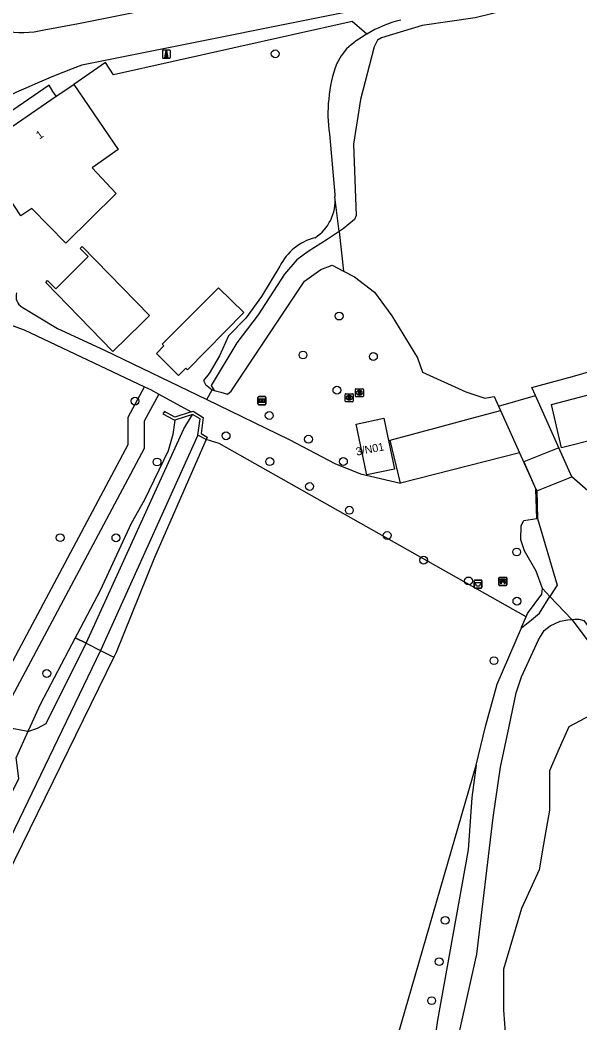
# Model space of a CAD drawing. Extents: x 164494 to 166241, y 382475 to 384494.
# Drawn here: x 165408.9 to 165478.8, y 383963 to 384088.3 of the extents above; entities that cross this region are included whole.
import ezdxf

# ---------------------------------------------------------------- set-up
doc = ezdxf.new("R2010")
doc.units = 0
for name, color, linetype in [('IMGEO_Afvalbak', 7, 'Continuous'), ('IMGEO_Bank', 7, 'Continuous'), ('IMGEO_Boom', 7, 'Continuous'), ('IMGEO_Erf', 7, 'Continuous'), ('IMGEO_Grasland_agrarisch', 7, 'Continuous'), ('IMGEO_Grasland_overig', 7, 'Continuous'), ('IMGEO_Groenvoorziening', 7, 'Continuous'), ('IMGEO_Informatiebord', 7, 'Continuous'), ('IMGEO_Kademuur', 7, 'Continuous'), ('IMGEO_Laagspanningsmast', 7, 'Continuous'), ('IMGEO_Loofbos', 7, 'Continuous'), ('IMGEO_Meer_plas_ven_vijver', 7, 'Continuous'), ('IMGEO_Muur', 7, 'Continuous'), ('IMGEO_Oever', 7, 'Continuous'), ('IMGEO_Pand', 7, 'Continuous'), ('IMGEO_Pand_nummerreeks', 7, 'Continuous'), ('IMGEO_Rijbaan_lokaal_gesloten', 7, 'Continuous'), ('IMGEO_Rioolput', 7, 'Continuous'), ('IMGEO_Rivier', 7, 'Continuous'), ('IMGEO_Stuw', 7, 'Continuous'), ('IMGEO_Voetpad_halfverhard', 7, 'Continuous'), ('IMGEO_Voetpad_open', 7, 'Continuous'), ('IMGEO_Waterloop', 7, 'Continuous')]:
    doc.layers.add(name, color=color, linetype=linetype)

msp = doc.modelspace()

# ---------------------------------------------------------------- linework, layer by layer
at = {"layer": 'IMGEO_Afvalbak'}
for p, q in [((165465.62, 384017.39), (165465.62, 384018.19)), ((165465.62, 384018.19), (165465.62, 384017.39)), ((165465.72, 384018.29), (165466.5, 384018.29)), ((165466.5, 384018.29), (165465.72, 384018.29)), ((165466.6, 384018.19), (165466.6, 384017.39)), ((165466.6, 384017.39), (165466.6, 384018.19)), ((165466.5, 384017.29), (165465.72, 384017.29)), ((165465.72, 384017.29), (165466.5, 384017.29))]:
    msp.add_line(p, q, dxfattribs=at)
msp.add_lwpolyline([(165465.76, 384018), (165466.46, 384018), (165466.31, 384017.53), (165465.91, 384017.53), (165465.76, 384018)], dxfattribs=at)
for centre, start, end in [((165465.72, 384018.19), 90, 180), ((165465.72, 384018.19), 90, 180), ((165466.5, 384018.19), 0, 90), ((165466.5, 384018.19), 360, 90), ((165465.72, 384017.39), 180, 270), ((165465.72, 384017.39), 180, 270), ((165466.5, 384017.39), 270, 0), ((165466.5, 384017.39), 270, 0)]:
    msp.add_arc(centre, 0.1, start, end, dxfattribs=at)
at = {"layer": 'IMGEO_Bank'}
for p, q in [((165468.72, 384017.69), (165468.72, 384018.54)), ((165468.72, 384018.54), (165468.72, 384017.69)), ((165468.79, 384018.62), (165469.63, 384018.62)), ((165469.63, 384018.62), (165468.79, 384018.62)), ((165469.41, 384018.02), (165469.02, 384018.02)), ((165469.03, 384018.13), (165469.03, 384018.23)), ((165469.07, 384018.23), (165469.07, 384018.13)), ((165469.36, 384018.24), (165469.08, 384018.24)), ((165469.08, 384018.12), (165469.36, 384018.12)), ((165469.36, 384018.13), (165469.36, 384018.23)), ((165469.41, 384018.23), (165469.41, 384018.13)), ((165469.72, 384018.55), (165469.72, 384017.7)), ((165469.72, 384017.7), (165469.72, 384018.55)), ((165469.64, 384017.62), (165468.8, 384017.62)), ((165468.8, 384017.62), (165469.64, 384017.62))]:
    msp.add_line(p, q, dxfattribs=at)
for points in [[(165468.96, 384018.02), (165468.82, 384018.02), (165468.93, 384018.12), (165469.02, 384018.12)], [(165469.02, 384018.24), (165468.93, 384018.24), (165468.93, 384018.4), (165469.5, 384018.4), (165469.5, 384018.24), (165469.41, 384018.24)], [(165469.01, 384018.01), (165469.01, 384017.8), (165468.97, 384017.8), (165468.97, 384018.01)], [(165469.41, 384018.12), (165469.5, 384018.12), (165469.61, 384018.02), (165469.47, 384018.02)], [(165469.46, 384018.01), (165469.46, 384017.8), (165469.42, 384017.8), (165469.42, 384018.01)]]:
    msp.add_lwpolyline(points, dxfattribs=at)
for centre, radius, start, end in [((165468.79, 384018.54), 0.0779, 92.4484, 184.2845), ((165468.79, 384018.54), 0.0779, 92.4484, 184.2845), ((165468.96, 384018.01), 0.00671, 2.8957, 87.1043), ((165469.02, 384018.01), 0.00671, 92.8957, 177.1043), ((165469.02, 384018.23), 0.00671, 2.8957, 87.1043), ((165469.02, 384018.13), 0.00671, 272.8957, 357.1043), ((165469.08, 384018.23), 0.00671, 92.8957, 177.1043), ((165469.08, 384018.13), 0.00671, 182.8957, 267.1043), ((165469.36, 384018.23), 0.00671, 2.8957, 87.1043), ((165469.36, 384018.13), 0.00671, 272.8957, 357.1043), ((165469.41, 384018.23), 0.00671, 92.8957, 177.1043), ((165469.41, 384018.13), 0.00671, 182.8957, 267.1043), ((165469.41, 384018.01), 0.00671, 2.8957, 87.1043), ((165469.47, 384018.01), 0.00671, 92.8957, 177.1043), ((165469.64, 384018.54), 0.0779, 2.4484, 94.2845), ((165469.64, 384018.54), 0.0779, 2.4484, 94.2845), ((165468.79, 384017.7), 0.0779, 182.4484, 274.2845), ((165468.79, 384017.7), 0.0779, 182.4484, 274.2845), ((165469.64, 384017.7), 0.0779, 272.4484, 4.2845), ((165469.64, 384017.7), 0.0779, 272.4484, 4.2845)]:
    msp.add_arc(centre, radius, start, end, dxfattribs=at)
at = {"layer": 'IMGEO_Boom'}
for centre in [(165440.77, 384084.04), (165448.76, 384051.27), (165444.24, 384046.41), (165453.04, 384046.21), (165448.48, 384042.01), (165423.25, 384040.64), (165440.02, 384038.84), (165434.63, 384036.31), (165444.93, 384035.88), (165426.01, 384033.03), (165440.09, 384033.09), (165449.29, 384033.1), (165445.06, 384029.98), (165450.03, 384027.01), (165413.91, 384023.58), (165420.87, 384023.56), (165454.76, 384023.86), (165470.94, 384021.8), (165459.32, 384020.77), (165464.92, 384018.18), (165470.97, 384015.65), (165468.1, 384008.22), (165412.23, 384006.62), (165462.01, 383975.77), (165461.26, 383970.61), (165460.32, 383965.74)]:
    msp.add_circle(centre, 0.489, dxfattribs=at)
at = {"layer": 'IMGEO_Erf'}
for points in [[(165449.69, 384084.66), (165448.99, 384083.8), (165448.46, 384082.83)], [(165447.55, 384074.05), (165448.2, 384066.46), (165448.24, 384066.18)], [(165441.35, 384057.51), (165439.04, 384053.71), (165437.08, 384051), (165434.93, 384048.82), (165433.83, 384046.32), (165432.51, 384044.11), (165431.83, 384043.24), (165432.06, 384042.7), (165432.89, 384042.04)]]:
    msp.add_lwpolyline(points, dxfattribs=at)
for centre, radius, start, end in [((165460.36, 384072.73), 16.01, 120.6716, 131.8064), ((165464.09, 384076.96), 16.7, 159.419, 175.1062), ((165464.24, 384076.59), 16.88, 173.9109, 188.6552), ((165442.76, 384065.68), 5.5, 302.8365, 5.2124), ((165447.45, 384054.45), 6.83, 104.5317, 153.3804)]:
    msp.add_arc(centre, radius, start, end, dxfattribs=at)
at = {"layer": 'IMGEO_Grasland_agrarisch'}
for points in [[(165432.13, 384035.84), (165425.7, 384021.1), (165420.91, 384009.22), (165420.6, 384008.64)], [(165471.52, 384012.31), (165471.56, 384012.41), (165472.11, 384013.7)], [(165420.6, 384008.64), (165397.65, 383961.84), (165387.56, 383941.91)]]:
    msp.add_lwpolyline(points, dxfattribs=at)
at = {"layer": 'IMGEO_Grasland_overig'}
for points in [[(165404.24, 384001.22), (165422.41, 384035.22), (165422.41, 384038.64), (165424.44, 384042.44)], [(165426.22, 384041.52), (165424.41, 384038.14), (165424.41, 384034.72), (165406.11, 384000.48)]]:
    msp.add_lwpolyline(points, dxfattribs=at)
at = {"layer": 'IMGEO_Groenvoorziening'}
for points in [[(165452.2, 384086.5), (165450.37, 384088.08), (165420.58, 384081.41), (165419.58, 384082.94), (165415.6, 384080.22)], [(165413.42, 384078.73), (165413, 384079.33), (165412.51, 384080.13), (165404.07, 384074.33), (165403.55, 384075.18), (165393.46, 384068.19), (165394.61, 384066.34)], [(165432.21, 384040.83), (165432.89, 384042.04)], [(165432.89, 384042.04), (165433.16, 384041.98)], [(165428.23, 384038.26), (165427.99, 384036.47), (165427.4, 384034.45), (165424.46, 384028.31), (165422.77, 384025.34), (165418.89, 384016.97), (165416.08, 384011.62), (165415.79, 384011.09)], [(165474.15, 384017.24), (165475.1, 384016.25)], [(165415.79, 384011.09), (165411.41, 384002.76), (165410.16, 384000), (165409.88, 383999.37)]]:
    msp.add_lwpolyline(points, dxfattribs=at)
msp.add_arc((165460.37, 384072.72), 16.02, 104.1806, 120.6638, dxfattribs=at)
at = {"layer": 'IMGEO_Informatiebord'}
for p, q in [((165438.62, 384040.3), (165438.62, 384041.1)), ((165438.62, 384041.1), (165438.62, 384040.3)), ((165438.72, 384041.2), (165439.51, 384041.2)), ((165439.51, 384041.2), (165438.72, 384041.2)), ((165439.61, 384041.1), (165439.61, 384040.3)), ((165439.61, 384040.3), (165439.61, 384041.1)), ((165439.51, 384040.2), (165438.72, 384040.2)), ((165438.72, 384040.2), (165439.51, 384040.2))]:
    msp.add_line(p, q, dxfattribs=at)
for points in [[(165438.72, 384040.94), (165439.51, 384040.94), (165439.51, 384040.47), (165438.72, 384040.47), (165438.72, 384040.94)], [(165438.79, 384040.87), (165438.79, 384040.54), (165439.06, 384040.54), (165439.06, 384040.75), (165439.17, 384040.75), (165439.17, 384040.54), (165439.44, 384040.54), (165439.44, 384040.87), (165439.17, 384040.87), (165439.17, 384040.79), (165439.06, 384040.79), (165439.06, 384040.87), (165438.79, 384040.87)]]:
    msp.add_lwpolyline(points, dxfattribs=at)
for centre, start, end in [((165438.72, 384041.1), 90, 180), ((165438.72, 384041.1), 90, 180), ((165439.51, 384041.1), 0, 90), ((165439.51, 384041.1), 360, 90), ((165438.72, 384040.3), 180, 270), ((165438.72, 384040.3), 180, 270), ((165439.51, 384040.3), 270, 0), ((165439.51, 384040.3), 270, 0)]:
    msp.add_arc(centre, 0.1, start, end, dxfattribs=at)
at = {"layer": 'IMGEO_Kademuur'}
for points in [[(165473.35, 384029.64), (165473.45, 384029.42), (165473.55, 384025.97)], [(165473.45, 384025.98), (165473.35, 384029.64)], [(165473.55, 384025.97), (165473.45, 384025.98)]]:
    msp.add_lwpolyline(points, dxfattribs=at)
at = {"layer": 'IMGEO_Laagspanningsmast'}
for p, q in [((165426.67, 384084.41), (165426.67, 384083.57)), ((165426.67, 384084.41), (165426.67, 384083.57)), ((165427.59, 384084.5), (165426.75, 384084.5)), ((165427.59, 384084.5), (165426.75, 384084.5)), ((165427.12, 384084.18), (165427.07, 384083.93)), ((165427.12, 384084.19), (165427.21, 384084.19)), ((165427.16, 384084.1), (165427.12, 384084.18)), ((165427.13, 384084.18), (165427.17, 384084.11)), ((165427.21, 384084.18), (165427.13, 384084.18)), ((165427.17, 384084.11), (165427.21, 384084.18)), ((165427.22, 384084.18), (165427.17, 384084.1)), ((165427.27, 384083.93), (165427.22, 384084.18)), ((165427.67, 384083.58), (165427.67, 384084.42)), ((165427.67, 384083.58), (165427.67, 384084.42)), ((165426.76, 384083.5), (165427.6, 384083.5)), ((165426.76, 384083.5), (165427.6, 384083.5)), ((165427.33, 384083.61), (165427, 384083.61)), ((165427.06, 384083.9), (165427.01, 384083.64)), ((165427.01, 384083.64), (165427.16, 384083.8)), ((165427.17, 384083.79), (165427.02, 384083.63)), ((165427.02, 384083.63), (165427.32, 384083.63)), ((165427.16, 384083.8), (165427.06, 384083.9)), ((165427.07, 384083.93), (165427.16, 384084.1)), ((165427.07, 384083.91), (165427.17, 384083.81)), ((165427.26, 384083.91), (165427.07, 384083.91)), ((165427.17, 384084.09), (165427.08, 384083.93)), ((165427.08, 384083.93), (165427.26, 384083.93)), ((165427.17, 384084.1), (165427.27, 384083.93)), ((165427.26, 384083.93), (165427.17, 384084.09)), ((165427.17, 384083.81), (165427.26, 384083.91)), ((165427.32, 384083.63), (165427.17, 384083.79)), ((165427.27, 384083.9), (165427.18, 384083.8)), ((165427.18, 384083.8), (165427.32, 384083.64)), ((165427.32, 384083.64), (165427.27, 384083.9))]:
    msp.add_line(p, q, dxfattribs=at)
for points in [[(165427, 384083.61), (165426.99, 384083.55), (165426.97, 384083.55), (165427.14, 384084.44), (165427.17, 384084.45), (165427.19, 384084.44), (165427.37, 384083.55), (165427.34, 384083.55), (165427.33, 384083.61)], [(165427.21, 384084.19), (165427.17, 384084.43), (165427.12, 384084.19)]]:
    msp.add_lwpolyline(points, dxfattribs=at)
for centre, start, end in [((165426.75, 384084.42), 92.4484, 184.2845), ((165426.75, 384084.42), 92.4484, 184.2845), ((165427.59, 384084.42), 2.4484, 94.2845), ((165427.59, 384084.42), 2.4484, 94.2845), ((165426.75, 384083.58), 182.4484, 274.2845), ((165426.75, 384083.58), 182.4484, 274.2845), ((165427.59, 384083.58), 272.4484, 4.2845), ((165427.59, 384083.58), 272.4484, 4.2845)]:
    msp.add_arc(centre, 0.0779, start, end, dxfattribs=at)
at = {"layer": 'IMGEO_Loofbos'}
for points in [[(165477.83, 384013.38), (165482.39, 384007.27), (165486.63, 384002.04), (165487.13, 384001.42)], [(165432.52, 383879.96), (165465.88, 383995.16)]]:
    msp.add_lwpolyline(points, dxfattribs=at)
at = {"layer": 'IMGEO_Meer_plas_ven_vijver'}
msp.add_lwpolyline([(165480.2, 384001.42), (165477.44, 383999.97), (165476.1, 383996.88), (165475.04, 383994.47), (165475.04, 383989.53), (165474.3, 383985.31), (165473.73, 383982.1), (165471.55, 383977.25), (165469.3, 383969.67), (165469.3, 383964.56), (165469.55, 383961.22), (165470.89, 383959.32), (165472.93, 383958.13), (165475.5, 383958.13), (165480.95, 383958.3)], dxfattribs=at)
at = {"layer": 'IMGEO_Muur'}
for points in [[(165430.27, 384039.31), (165428.21, 384038.62), (165426.94, 384039.34), (165426.75, 384039.04), (165428.08, 384038.34), (165428.23, 384038.26)], [(165430.27, 384039.31), (165430.5, 384039.39), (165431.77, 384038.6), (165431.52, 384036.59), (165432.26, 384036.16), (165432.13, 384035.84)], [(165430.45, 384038.96), (165428.23, 384038.26)], [(165431.12, 384036.4), (165431.4, 384038.43), (165430.45, 384038.96)], [(165432.13, 384035.84), (165431.12, 384036.4)]]:
    msp.add_lwpolyline(points, dxfattribs=at)
at = {"layer": 'IMGEO_Oever'}
for points in [[(165448.74, 384061.82), (165448.24, 384066.18)], [(165417.14, 384010.41), (165415.79, 384011.09)], [(165418.94, 384009.5), (165420.6, 384008.64)]]:
    msp.add_lwpolyline(points, dxfattribs=at)
at = {"layer": 'IMGEO_Pand'}
for points in [[(165415.6, 384080.22), (165421.16, 384072.09), (165417.91, 384069.8), (165420.92, 384066.58), (165414.62, 384060.38), (165410.36, 384064.72), (165408.99, 384063.79), (165403.58, 384072), (165413.42, 384078.73)], [(165413.42, 384078.73), (165415.6, 384080.22)], [(165424.1, 384050.37), (165420.47, 384046.84), (165412.1, 384055.45), (165412.34, 384055.7), (165413.35, 384054.69), (165417.39, 384058.72), (165416.39, 384059.72), (165416.64, 384059.97), (165425.07, 384051.32), (165424.1, 384050.37)], [(165425.93, 384046.61), (165426.86, 384047.53), (165426.65, 384047.74), (165433.7, 384054.8), (165436.84, 384051.71), (165429.8, 384044.56), (165429.59, 384044.77), (165428.67, 384043.86), (165425.93, 384046.61)], [(165491.94, 384044.59), (165494.08, 384034.6), (165485.88, 384032.75), (165485.64, 384034.07), (165485.11, 384036.98), (165476.53, 384034.79), (165475.28, 384040.21), (165482.1, 384042.01), (165491.94, 384044.59)], [(165456.43, 384030.39), (165455.12, 384035.77), (165461.8, 384037.57), (165464.71, 384038.34), (165468.92, 384039.47)], [(165468.92, 384039.47), (165470.96, 384034.95), (165471.3, 384034.18)], [(165452.19, 384031.58), (165450.88, 384037.77), (165454.35, 384038.53), (165454.93, 384035.72), (165455.67, 384032.14), (165452.22, 384031.44), (165452.19, 384031.58)], [(165471.3, 384034.18), (165456.43, 384030.39)]]:
    msp.add_lwpolyline(points, dxfattribs=at)
at = {"layer": 'IMGEO_Rijbaan_lokaal_gesloten'}
for points in [[(165411.91, 384087.02), (165416.2, 384087.82), (165455.96, 384095.8)], [(165456.98, 384090.71), (165416.61, 384082.6)]]:
    msp.add_lwpolyline(points, dxfattribs=at)
for centre, radius, start, end in [((165408.98, 384099.66), 12.97, 260.4155, 283.0716), ((165456.82, 383973.93), 115.88, 110.3071, 120.2751)]:
    msp.add_arc(centre, radius, start, end, dxfattribs=at)
at = {"layer": 'IMGEO_Rioolput'}
for p, q in [((165450.79, 384041.26), (165450.79, 384042.11)), ((165450.86, 384042.19), (165451.71, 384042.19)), ((165451.28, 384041.96), (165451.3, 384041.96)), ((165451.79, 384042.11), (165451.79, 384041.26)), ((165449.52, 384040.64), (165449.52, 384041.49)), ((165449.59, 384041.57), (165450.44, 384041.57)), ((165450.44, 384040.57), (165449.59, 384040.57)), ((165450.03, 384040.79), (165450, 384040.79)), ((165450.01, 384041.35), (165450.03, 384041.35)), ((165450.52, 384041.49), (165450.52, 384040.64)), ((165451.71, 384041.18), (165450.86, 384041.18)), ((165451.3, 384041.41), (165451.27, 384041.41))]:
    msp.add_line(p, q, dxfattribs=at)
for points in [[(165450.79, 384041.26), (165450.79, 384042.11)], [(165450.86, 384042.19), (165451.71, 384042.19)], [(165451.38, 384041.88), (165451.12, 384041.88), (165451.12, 384041.48)], [(165451.12, 384041.48), (165451.25, 384041.48), (165451.25, 384041.65), (165451.26, 384041.65)], [(165451.3, 384041.8), (165451.25, 384041.8), (165451.25, 384041.72)], [(165451.25, 384041.72), (165451.3, 384041.72)], [(165451.31, 384041.62), (165451.38, 384041.48), (165451.52, 384041.48), (165451.45, 384041.61)], [(165451.79, 384042.11), (165451.79, 384041.26)], [(165449.52, 384040.64), (165449.52, 384041.49)], [(165449.59, 384041.57), (165450.44, 384041.57)], [(165450.44, 384040.57), (165449.59, 384040.57)], [(165450.11, 384041.26), (165449.85, 384041.27), (165449.85, 384040.87)], [(165449.85, 384040.87), (165449.98, 384040.87), (165449.98, 384041.03), (165449.99, 384041.03)], [(165450.03, 384041.19), (165449.98, 384041.19), (165449.98, 384041.1)], [(165449.98, 384041.1), (165450.03, 384041.1)], [(165450.04, 384041), (165450.11, 384040.87), (165450.25, 384040.87), (165450.18, 384040.99)], [(165450.52, 384041.49), (165450.52, 384040.64)], [(165451.71, 384041.18), (165450.86, 384041.18)]]:
    msp.add_lwpolyline(points, dxfattribs=at)
for centre, radius, start, end in [((165450.86, 384042.11), 0.0765, 91.552, 178.448), ((165450.86, 384042.11), 0.0765, 91.552, 178.448), ((165451.26, 384041.59), 0.0533, 26.0293, 88.6989), ((165451.31, 384041.71), 0.0964, 77.0061, 93.1865), ((165451.28, 384041.91), 0.19, 274.7715, 282.9687), ((165451.32, 384041.76), 0.0378, 276.6634, 79.6772), ((165451.38, 384041.77), 0.109, 350.3612, 89.416), ((165451.37, 384041.77), 0.112, 277.5842, 350.9817), ((165451.36, 384041.56), 0.108, 29.5134, 73.7905), ((165451.71, 384042.11), 0.0765, 1.552, 88.448), ((165451.71, 384042.11), 0.0765, 1.552, 88.448), ((165449.59, 384041.49), 0.0765, 91.552, 178.448), ((165449.59, 384041.49), 0.0765, 91.552, 178.448), ((165449.59, 384040.64), 0.0765, 181.552, 268.448), ((165449.59, 384040.64), 0.0765, 181.552, 268.448), ((165449.99, 384040.98), 0.0533, 26.0293, 88.6989), ((165450.04, 384041.09), 0.0964, 77.0061, 93.1865), ((165450.01, 384041.29), 0.19, 274.7715, 282.9687), ((165450.05, 384041.15), 0.0378, 276.6634, 79.6772), ((165450.11, 384041.15), 0.109, 350.3612, 89.416), ((165450.1, 384041.15), 0.112, 277.5842, 350.9817), ((165450.09, 384040.94), 0.108, 29.5134, 73.7905), ((165450.44, 384041.49), 0.0765, 1.552, 88.448), ((165450.44, 384041.49), 0.0765, 1.552, 88.448), ((165450.44, 384040.64), 0.0765, 271.552, 358.448), ((165450.44, 384040.64), 0.0765, 271.552, 358.448), ((165450.86, 384041.26), 0.0765, 181.552, 268.448), ((165450.86, 384041.26), 0.0765, 181.552, 268.448), ((165451.71, 384041.26), 0.0765, 271.552, 358.448), ((165451.71, 384041.26), 0.0765, 271.552, 358.448)]:
    msp.add_arc(centre, radius, start, end, dxfattribs=at)
for centre, major_axis, ratio, start_param, end_param in [((165451.27, 384041.68), (-0.387, 0.002), 0.722429, 4.712389, 7.853982), ((165451.3, 384041.68), (-0.39, 0.002), 0.717154, 1.570796, 4.712389), ((165450, 384041.07), (-0.387, 0.002), 0.722429, 4.712389, 7.853982), ((165450.03, 384041.07), (-0.39, 0.002), 0.717154, 1.570796, 4.712389)]:
    msp.add_ellipse(centre, major_axis=major_axis, ratio=ratio, start_param=start_param, end_param=end_param, dxfattribs=at)
at = {"layer": 'IMGEO_Rivier'}
for points in [[(165474.83, 384091.12), (165469.52, 384089.43), (165465.75, 384088.54), (165459.14, 384087.57), (165454.07, 384086.05), (165453.57, 384085.73), (165453.13, 384084.89), (165451.41, 384078.33), (165450.57, 384072.76), (165450.89, 384063.84), (165450.66, 384063.34), (165449.28, 384062.17), (165448.74, 384061.82)], [(165473.27, 384041.33), (165472.82, 384042.34), (165473.75, 384042.59), (165477.9, 384043.72), (165483.77, 384045.44), (165486.01, 384048.77), (165487.52, 384053.23), (165488.1, 384062.16), (165487.05, 384069.95), (165486.01, 384074.23), (165486.3, 384078.74), (165489.65, 384082.75), (165493.52, 384085.76), (165495.37, 384086.22), (165499.76, 384086.15), (165510.96, 384086.71), (165512.96, 384086.35), (165513.67, 384084.92)], [(165448.74, 384061.82), (165449.32, 384056.89)], [(165449.32, 384056.89), (165450.67, 384056.19), (165453.18, 384054.24), (165455.36, 384051.28), (165458.53, 384046.07), (165459.18, 384044.24), (165464.57, 384041.81), (165466.96, 384041.03), (165468.13, 384041.22), (165468.68, 384040)], [(165468.68, 384040), (165473.27, 384041.33)], [(165554.47, 383924.18), (165553.46, 383924.3), (165551.79, 383925.29), (165548.66, 383927.88), (165543.58, 383932.37), (165541.37, 383934.81), (165535.29, 383951.85), (165527.54, 383967.82), (165514.92, 383987.28), (165498.19, 384008.96), (165488.46, 384021.89), (165477.84, 384031.18), (165473.27, 384041.33)], [(165468.68, 384040), (165468.92, 384039.47)], [(165473.55, 384025.97), (165476, 384017.67), (165475.1, 384016.25)], [(165475.1, 384016.25), (165477.83, 384013.38)], [(165477.83, 384013.38), (165478.22, 384013.42), (165478.69, 384013.39), (165479.32, 384013.23), (165481.89, 384009.78), (165483.64, 384007.37), (165485.78, 384004.64), (165486.29, 384003.59), (165486.43, 384003.01), (165486.83, 384002.56), (165487.34, 384001.98), (165487.38, 384001.58), (165487.23, 384001.3)]]:
    msp.add_lwpolyline(points, dxfattribs=at)
at = {"layer": 'IMGEO_Stuw'}
for points in [[(165468.68, 384040), (165473.27, 384041.33)], [(165415.79, 384011.09), (165417.14, 384010.41), (165418.94, 384009.5), (165420.6, 384008.64)]]:
    msp.add_lwpolyline(points, dxfattribs=at)
at = {"layer": 'IMGEO_Voetpad_halfverhard'}
for points in [[(165409.16, 384052.4), (165413.57, 384049.73), (165419.45, 384047), (165432.21, 384040.83)], [(165405.91, 384050.79), (165409.42, 384049.54), (165424.44, 384042.44)], [(165424.44, 384042.44), (165425.17, 384042.09), (165426.22, 384041.52)], [(165426.22, 384041.52), (165430.27, 384039.31)], [(165432.21, 384040.83), (165442.52, 384035.84), (165448.2, 384032.84), (165451.41, 384031.56), (165456.43, 384030.39)], [(165472.11, 384013.7), (165433.76, 384035.36), (165432.13, 384035.84)], [(165471.3, 384034.18), (165473.35, 384029.64)], [(165474.15, 384017.24), (165473.36, 384019.39), (165471.92, 384021.92), (165471.47, 384023.3), (165471.5, 384025.12), (165471.84, 384025.74), (165473.45, 384025.98)], [(165472.11, 384013.7), (165472.3, 384014.13), (165474.1, 384016.54), (165474.15, 384017.24)]]:
    msp.add_lwpolyline(points, dxfattribs=at)
msp.add_arc((165409.86, 384053.69), 1.47, 161.3303, 241.2683, dxfattribs=at)
at = {"layer": 'IMGEO_Voetpad_open'}
msp.add_lwpolyline([(165476.21, 384034.8), (165471.82, 384033.04), (165473.35, 384029.64), (165473.45, 384029.42), (165477.84, 384031.18), (165476.21, 384034.8)], dxfattribs=at)
at = {"layer": 'IMGEO_Waterloop'}
for points in [[(165448.74, 384061.82), (165447.28, 384060.84), (165444.88, 384059.34), (165443.48, 384058.29), (165441.93, 384056.51), (165438.65, 384051.43), (165435.98, 384047.93), (165432.76, 384042.61), (165433.16, 384041.98)], [(165433.16, 384041.98), (165433.99, 384041.78), (165434.8, 384041.5), (165435.26, 384041.87), (165444.41, 384055.62), (165446.49, 384057.1), (165447.89, 384057.63), (165449.32, 384056.89)], [(165417.14, 384010.41), (165429.34, 384037.19), (165430.45, 384038.96)], [(165431.12, 384036.4), (165419.21, 384010.04), (165418.94, 384009.5)], [(165471.52, 384012.31), (165472.77, 384013.33), (165473.78, 384014.16), (165475.1, 384016.25)], [(165461.63, 383952.12), (165465.96, 383971.55), (165468.02, 383988.64), (165468.92, 383994.91), (165469.99, 384000), (165470.87, 384004.18), (165471.56, 384006.19), (165473.68, 384010.82), (165474.39, 384012), (165475.11, 384012.55), (165476.38, 384013.16), (165477.33, 384013.33), (165477.83, 384013.38)], [(165465.88, 383995.16), (165467.03, 384000), (165468.5, 384005.26), (165471.52, 384012.31)], [(165409.88, 383999.37), (165411.09, 383999.78), (165412.14, 384000.35), (165417.14, 384010.41)], [(165417.14, 384010.41), (165418.94, 384009.5)], [(165418.94, 384009.5), (165387.35, 383943.88), (165386.8, 383943.09), (165386.05, 383942.89), (165385.32, 383942.89), (165384.83, 383943.19), (165384.5, 383943.65), (165384.33, 383944.04), (165384.41, 383944.72), (165387.06, 383949.94), (165408.72, 383993.48), (165408.4, 383996.12)], [(165409.88, 383999.37), (165408.11, 383999.68), (165407.3, 384000), (165406.11, 384000.48)], [(165409.88, 383999.37), (165408.4, 383996.12)], [(165465.88, 383995.16), (165465.35, 383991.14), (165464.89, 383984.58), (165461.03, 383963.29), (165460.17, 383957.17), (165458.08, 383944.29), (165457.76, 383939.31), (165457.26, 383937.11), (165453.99, 383927.19), (165452.71, 383923.88), (165447.81, 383915.92), (165446.1, 383912.87), (165442.98, 383906.73), (165439.15, 383897.48), (165438.16, 383893.3), (165437.01, 383889.83), (165432.52, 383879.96)]]:
    msp.add_lwpolyline(points, dxfattribs=at)

# ---------------------------------------------------------------- texts
at = {"layer": 'IMGEO_Pand_nummerreeks'}
for s, rotation, p in [('1', 34.3689, (165411.31, 384073.31)), ('3/N01', 11.1006, (165450.95, 384033.82))]:
    msp.add_text(s, height=1, rotation=rotation, dxfattribs=at).set_placement(p)

doc.saveas('drawing.dxf')
